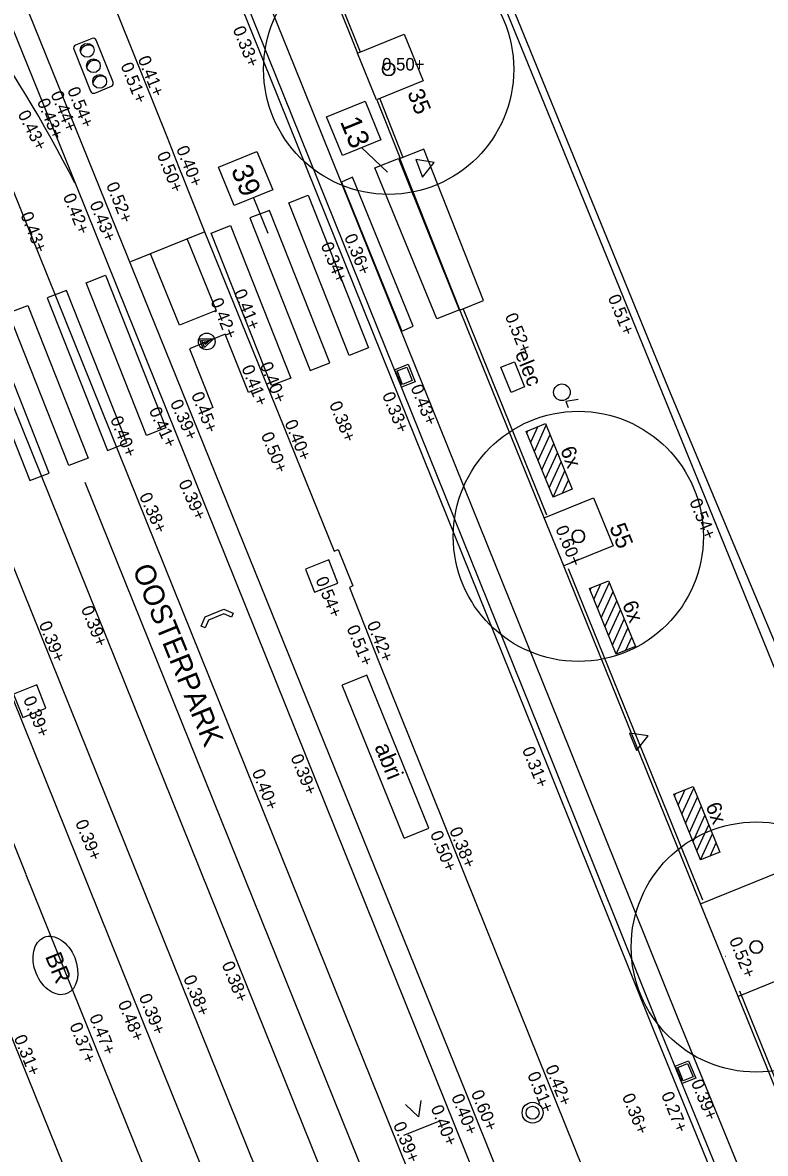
# Model space of a CAD drawing. Extents: x 122462 to 123306, y 485548 to 486417.
# Drawn here: x 122945.6 to 122963.41, y 485781.02 to 485808.14 of the extents above; entities that cross this region are included whole.
import ezdxf

# ---------------------------------------------------------------- set-up
doc = ezdxf.new("R2010")
doc.units = 0
for name, color, linetype in [('B meubilair trammast', 7, 'Continuous'), ('B-WE-AL-T25', 7, 'Continuous'), ('B-WE-GR-BOOM_BOOMDIAMETER', 7, 'Continuous'), ('B-WE-IE-MEUBILAIR_ELECTRAKAST', 7, 'Continuous'), ('B-WE-IE-MEUBILAIR_FIETSENREK-S', 7, 'Continuous'), ('B-WE-IE-TERREINAFSCHEIDING_KUNSTMATIG_HEKWERK-G', 7, 'Continuous'), ('B-WE-KL-ET_LS_OV_LICHTMAST-S', 7, 'Continuous'), ('B-WE-OG-HOOGTEPUNT-S', 7, 'Continuous'), ('B-WE-OG-TOPOGRAFIE_STRAATNAAM', 7, 'Continuous'), ('B-WE-RI-HWA_KOLK-S', 7, 'Continuous'), ('B-WE-RI-HWA_RIOOLPUT-S', 7, 'Continuous'), ('B-WE-VH-KANTOPSLUITING_OPSLUITBAND_100X200-G', 7, 'Continuous'), ('B-WE-VH-KANTOPSLUITING_TROTTOIRBAND_130 150-G', 7, 'Continuous'), ('B-WE-VH-MATERIAALGRENS-G', 7, 'Continuous'), ('B-WE-VH-MATERIAALGRENS_ASFALT-G', 7, 'Continuous'), ('B-WE-VW-MARKERING_LANGS_STREEP_30_15-30-G', 7, 'Continuous'), ('B-WE-VW-MARKERING_LANGS_STREEP_DOORGETROKKEN_010-G', 7, 'Continuous'), ('iba7-verkeersbord blauw', 7, 'Continuous'), ('iba7-verkeersbord rood', 7, 'Continuous'), ('N-WE-IE-MEUBILAIR_ABRI-S', 7, 'Continuous'), ('V boomranden', 7, 'Continuous'), ('V Langsstreep 030-015', 7, 'Continuous'), ('V markering figuratie', 7, 'Continuous'), ('V markering ononderbroken streep 10 cm', 7, 'Continuous'), ('V materiaalscheiding algemeen', 7, 'Continuous'), ('V meubilair trammast', 7, 'Continuous'), ('V meubilair verkeersbord', 7, 'Continuous'), ('V meubilair verkeerslicht', 7, 'Continuous'), ('V Rails', 7, 'Continuous'), ('V riool inspectieput', 7, 'Continuous'), ('V trottoirband 180-200x250 mm specie', 7, 'Continuous'), ('V-WE-GR-BOOM-S', 7, 'Continuous'), ('X-WE-AL-TEKENBLAD-S', 7, 'Continuous')]:
    doc.layers.add(name, color=color, linetype=linetype)

msp = doc.modelspace()

# ---------------------------------------------------------------- linework, layer by layer
at = {"layer": 'B meubilair trammast'}
msp.add_lwpolyline([(122960.157, 485791.095), (122960.326, 485790.678), (122960.603, 485791.033)], close=True, dxfattribs=at)
at = {"layer": 'B-WE-IE-MEUBILAIR_ELECTRAKAST'}
for p, q in [((122957.071, 485799.873), (122957.395, 485800.004)), ((122957.395, 485800.004), (122957.64, 485799.402)), ((122957.316, 485799.271), (122957.071, 485799.873)), ((122957.64, 485799.402), (122957.316, 485799.271))]:
    msp.add_line(p, q, dxfattribs=at)
at = {"layer": 'B-WE-IE-MEUBILAIR_FIETSENREK-S'}
for p, q in [((122957.679, 485798.333), (122958.142, 485798.522)), ((122958.32, 485796.759), (122957.679, 485798.333)), ((122957.696, 485798.291), (122957.723, 485798.352)), ((122957.785, 485798.073), (122957.955, 485798.446)), ((122957.874, 485797.854), (122958.159, 485798.48)), ((122958.142, 485798.522), (122958.783, 485796.947)), ((122957.963, 485797.635), (122958.248, 485798.26)), ((122958.052, 485797.416), (122958.337, 485798.042)), ((122958.141, 485797.197), (122958.426, 485797.823)), ((122958.231, 485796.978), (122958.516, 485797.603)), ((122958.32, 485796.759), (122958.605, 485797.385)), ((122958.783, 485796.947), (122958.32, 485796.759)), ((122958.551, 485796.853), (122958.694, 485797.166)), ((122959.192, 485794.564), (122959.655, 485794.753)), ((122959.655, 485794.753), (122960.296, 485793.178)), ((122959.833, 485792.989), (122959.192, 485794.564)), ((122959.209, 485794.522), (122959.237, 485794.582)), ((122959.298, 485794.303), (122959.468, 485794.676)), ((122959.388, 485794.085), (122959.673, 485794.711)), ((122959.477, 485793.865), (122959.762, 485794.491)), ((122959.566, 485793.646), (122959.851, 485794.272)), ((122959.655, 485793.428), (122959.94, 485794.054)), ((122959.744, 485793.208), (122960.029, 485793.834)), ((122959.833, 485792.989), (122960.118, 485793.615)), ((122960.065, 485793.084), (122960.207, 485793.397)), ((122960.296, 485793.178), (122959.833, 485792.989)), ((122961.218, 485789.632), (122961.681, 485789.82)), ((122961.859, 485788.057), (122961.218, 485789.632)), ((122961.235, 485789.59), (122961.262, 485789.65)), ((122961.324, 485789.371), (122961.494, 485789.744)), ((122961.413, 485789.152), (122961.698, 485789.778)), ((122961.681, 485789.82), (122962.322, 485788.246)), ((122961.502, 485788.933), (122961.787, 485789.559)), ((122961.591, 485788.714), (122961.876, 485789.34)), ((122961.68, 485788.495), (122961.965, 485789.121)), ((122961.77, 485788.276), (122962.055, 485788.902)), ((122961.859, 485788.057), (122962.144, 485788.683)), ((122962.322, 485788.246), (122961.859, 485788.057)), ((122962.09, 485788.151), (122962.233, 485788.464))]:
    msp.add_line(p, q, dxfattribs=at)
at = {"layer": 'B-WE-IE-TERREINAFSCHEIDING_KUNSTMATIG_HEKWERK-G'}
msp.add_lwpolyline([(122989.165, 485730.709), (122983.361, 485744.921), (122981.681, 485749.067), (122980.156, 485752.878), (122979.412, 485754.737), (122974.855, 485765.867), (122973.315, 485769.586), (122971.781, 485773.305), (122965.757, 485788.22), (122961.098, 485799.347), (122955.791, 485812.34), (122952.781, 485819.767), (122949.963, 485826.635), (122951.345, 485827.208)], dxfattribs=at)
at = {"layer": 'B-WE-KL-ET_LS_OV_LICHTMAST-S'}
msp.add_lwpolyline([(122958.924, 485799.101), (122958.629, 485799.048), (122958.686, 485798.909)], dxfattribs=at)
msp.add_circle((122958.534, 485799.273), 0.2, dxfattribs=at)
at = {"layer": 'B-WE-RI-HWA_KOLK-S'}
for p, q in [((122954.517, 485799.813), (122954.842, 485799.943)), ((122954.842, 485799.943), (122955.01, 485799.526)), ((122954.685, 485799.395), (122954.517, 485799.813)), ((122954.536, 485799.766), (122954.54, 485799.768)), ((122954.583, 485799.688), (122954.553, 485799.763)), ((122954.573, 485799.673), (122954.578, 485799.675)), ((122954.582, 485799.65), (122954.587, 485799.652)), ((122954.63, 485799.572), (122954.6, 485799.647)), ((122954.62, 485799.558), (122954.625, 485799.559)), ((122954.629, 485799.534), (122954.634, 485799.536)), ((122954.659, 485799.5), (122954.647, 485799.531)), ((122954.677, 485799.456), (122954.659, 485799.5)), ((122954.667, 485799.442), (122954.671, 485799.443)), ((122955.01, 485799.526), (122954.685, 485799.395)), ((122961.249, 485783.109), (122961.573, 485783.242)), ((122961.419, 485782.693), (122961.249, 485783.109)), ((122961.573, 485783.242), (122961.743, 485782.825)), ((122961.268, 485783.063), (122961.272, 485783.065)), ((122961.315, 485782.985), (122961.285, 485783.059)), ((122961.305, 485782.97), (122961.31, 485782.972)), ((122961.315, 485782.947), (122961.319, 485782.949)), ((122961.363, 485782.87), (122961.332, 485782.944)), ((122961.353, 485782.855), (122961.357, 485782.857)), ((122961.362, 485782.832), (122961.367, 485782.833)), ((122961.392, 485782.797), (122961.38, 485782.828)), ((122961.743, 485782.825), (122961.419, 485782.693)), ((122961.41, 485782.754), (122961.392, 485782.797)), ((122961.4, 485782.739), (122961.404, 485782.741))]:
    msp.add_line(p, q, dxfattribs=at)
for points in [[(122954.814, 485799.878), (122954.945, 485799.554), (122954.713, 485799.46), (122954.582, 485799.785)], [(122961.545, 485783.176), (122961.678, 485782.852), (122961.446, 485782.758), (122961.314, 485783.082)]]:
    msp.add_lwpolyline(points, close=True, dxfattribs=at)
for centre, start, end in [((122954.544, 485799.759), 21.9526, 111.9526), ((122954.574, 485799.685), 291.9526, 21.9526), ((122954.591, 485799.643), 21.9526, 111.9526), ((122954.621, 485799.569), 291.9526, 21.9526), ((122954.638, 485799.527), 21.9526, 111.9526), ((122954.667, 485799.453), 291.9526, 21.9526), ((122961.276, 485783.056), 22.213, 112.213), ((122961.306, 485782.982), 292.213, 22.213), ((122961.323, 485782.94), 22.213, 112.213), ((122961.353, 485782.866), 292.213, 22.213), ((122961.37, 485782.824), 22.213, 112.213), ((122961.401, 485782.75), 292.213, 22.213)]:
    msp.add_arc(centre, 0.01, start, end, dxfattribs=at)
at = {"layer": 'B-WE-RI-HWA_RIOOLPUT-S'}
msp.add_lwpolyline([(122953.16, 485794.696), (122952.94, 485795.254), (122952.382, 485795.034), (122952.602, 485794.476)], close=True, dxfattribs=at)
at = {"layer": 'B-WE-VH-KANTOPSLUITING_OPSLUITBAND_100X200-G'}
msp.add_lwpolyline([(122973.186, 485769.183), (122961.88, 485796.965), (122957.179, 485808.478), (122950.921, 485823.807), (122951.367, 485823.988)], dxfattribs=at)
for points in [[(122958.108, 485796.262), (122959.293, 485796.743), (122959.761, 485795.588), (122958.576, 485795.108)], [(122961.859, 485787.008), (122963.789, 485787.789), (122964.691, 485785.563), (122962.761, 485784.781)]]:
    msp.add_lwpolyline(points, close=True, dxfattribs=at)
at = {"layer": 'B-WE-VH-KANTOPSLUITING_TROTTOIRBAND_130 150-G'}
for points in [[(122944.788, 485793.338), (122945.622, 485791.289), (122948.972, 485782.968), (122953.472, 485771.818)], [(122944.02, 485787.037), (122960.779, 485745.561)]]:
    msp.add_lwpolyline(points, dxfattribs=at)
at = {"layer": 'B-WE-VH-MATERIAALGRENS-G'}
for points in [[(122958.108, 485796.262), (122956.423, 485800.42)], [(122961.326, 485784.244), (122958.46, 485791.369), (122955.04, 485799.854)], [(122961.859, 485787.008), (122958.57, 485795.123)], [(122965.926, 485776.976), (122962.763, 485784.779)], [(122983.898, 485728.575), (122964.99, 485775.27), (122961.325, 485784.246)]]:
    msp.add_lwpolyline(points, dxfattribs=at)
at = {"layer": 'B-WE-VH-MATERIAALGRENS_ASFALT-G'}
for points in [[(122954.438, 485799.608), (122957.857, 485791.126), (122960.723, 485784.001)], [(122960.723, 485784.001), (122964.388, 485775.026), (122983.295, 485728.331)]]:
    msp.add_lwpolyline(points, dxfattribs=at)
at = {"layer": 'B-WE-VW-MARKERING_LANGS_STREEP_30_15-30-G'}
for points in [[(122958.17, 485796.328), (122956.499, 485800.451)], [(122961.914, 485787.091), (122958.694, 485795.035)], [(122962.462, 485785.739), (122962.461, 485785.742)], [(122965.966, 485777.094), (122962.798, 485784.908)]]:
    msp.add_lwpolyline(points, dxfattribs=at)
at = {"layer": 'B-WE-VW-MARKERING_LANGS_STREEP_DOORGETROKKEN_010-G'}
for points in [[(122955.152, 485782.289), (122955.096, 485781.892), (122954.783, 485782.189)], [(122954.738, 485781.453), (122955.649, 485781.817)]]:
    msp.add_lwpolyline(points, dxfattribs=at)
at = {"layer": 'iba7-verkeersbord blauw'}
for radius in [0.25, 0.156]:
    msp.add_circle((122957.83, 485781.995), radius, dxfattribs=at)
msp.add_ellipse((122946.384, 485785.526), major_axis=(-0.273, 0.676), ratio=0.685994, dxfattribs=at)
at = {"layer": 'iba7-verkeersbord rood'}
for centre, radius in [((122954.378, 485807.018), 3), ((122954.378, 485807.018), 0.15), ((122958.928, 485795.816), 3), ((122958.928, 485795.816), 0.15), ((122963.195, 485785.968), 3), ((122963.195, 485785.968), 0.15)]:
    msp.add_circle(centre, radius, dxfattribs=at)
for centre, start, end in [((122954.378, 485807.018), 0, 180), ((122954.378, 485807.018), 180, 0), ((122958.928, 485795.816), 0, 180), ((122958.928, 485795.816), 180, 0), ((122963.195, 485785.968), 0, 180), ((122963.195, 485785.968), 180, 0)]:
    msp.add_arc(centre, 0.15, start, end, dxfattribs=at)
at = {"layer": 'N-WE-IE-MEUBILAIR_ABRI-S'}
msp.add_line((122954.748, 485788.577), (122953.26, 485792.249), dxfattribs=at)
msp.add_lwpolyline([(122954.748, 485788.577), (122955.343, 485788.818), (122953.856, 485792.49), (122953.26, 485792.249)], dxfattribs=at)
at = {"layer": 'V boomranden'}
msp.add_lwpolyline([(122953.633, 485807.408), (122954.753, 485807.862), (122955.208, 485806.738), (122954.088, 485806.285)], close=True, dxfattribs=at)
at = {"layer": 'V Langsstreep 030-015'}
for points in [[(122949.775, 485817.2), (122953.698, 485807.434)], [(122954.163, 485806.313), (122954.71, 485804.93)], [(122956.499, 485800.451), (122956.163, 485801.279)]]:
    msp.add_lwpolyline(points, dxfattribs=at)
at = {"layer": 'V markering figuratie'}
for p, q in [((122949.977, 485793.888), (122950.425, 485794.07)), ((122950.424, 485793.961), (122950.053, 485793.811)), ((122950.608, 485793.883), (122950.424, 485793.961)), ((122950.425, 485794.07), (122950.647, 485793.975)), ((122950.647, 485793.975), (122950.608, 485793.883)), ((122949.883, 485793.666), (122949.977, 485793.888)), ((122949.975, 485793.627), (122949.883, 485793.666)), ((122950.053, 485793.811), (122949.975, 485793.627))]:
    msp.add_line(p, q, dxfattribs=at)
for points in [[(122956.059, 485801.238), (122955.53, 485801.032), (122954.044, 485804.657), (122954.613, 485804.878), (122956.066, 485801.248)], [(122953.514, 485804.435), (122953.243, 485804.314), (122954.693, 485800.735), (122954.964, 485800.856), (122953.514, 485804.435)]]:
    msp.add_lwpolyline(points, dxfattribs=at)
for points in [[(122953.429, 485800.158), (122951.983, 485803.817), (122952.449, 485803.998), (122953.895, 485800.339)], [(122951.051, 485803.455), (122952.497, 485799.796), (122952.963, 485799.977), (122951.517, 485803.636)], [(122951.565, 485799.433), (122950.119, 485803.092), (122950.585, 485803.273), (122952.031, 485799.614)], [(122948.566, 485798.239), (122947.12, 485801.898), (122947.586, 485802.08), (122949.032, 485798.421)], [(122946.188, 485801.536), (122947.634, 485797.877), (122948.1, 485798.058), (122946.654, 485801.717)], [(122946.702, 485797.515), (122945.256, 485801.174), (122945.722, 485801.355), (122947.168, 485797.696)], [(122944.324, 485800.812), (122945.77, 485797.153), (122946.236, 485797.334), (122944.79, 485800.993)]]:
    msp.add_lwpolyline(points, close=True, dxfattribs=at)
at = {"layer": 'V markering ononderbroken streep 10 cm'}
msp.add_lwpolyline([(122960.179, 485764.685), (122947.097, 485797.105)], dxfattribs=at)
at = {"layer": 'V materiaalscheiding algemeen'}
for points in [[(122955.04, 485799.854), (122952.121, 485807.096), (122947.132, 485819.421), (122944.074, 485826.926), (122939.266, 485838.678), (122934.779, 485849.488)], [(122934.198, 485849.192), (122938.665, 485838.43), (122943.472, 485826.68), (122946.53, 485819.177), (122951.518, 485806.853), (122954.438, 485799.608)], [(122949.71, 485817.174), (122953.633, 485807.408)], [(122954.098, 485806.287), (122954.645, 485804.904)], [(122956.099, 485801.253), (122956.654, 485801.476), (122955.221, 485805.101), (122954.652, 485804.876)], [(122956.423, 485800.42), (122956.087, 485801.248), (122954.64, 485804.902)], [(122949.544, 485802.948), (122950.237, 485801.233), (122949.36, 485800.88), (122948.668, 485802.595)], [(122951.25, 485799.367), (122951.019, 485799.271), (122950.452, 485800.669), (122949.597, 485800.313), (122950.164, 485798.904), (122949.857, 485798.773)]]:
    msp.add_lwpolyline(points, dxfattribs=at)
at = {"layer": 'V meubilair trammast'}
msp.add_lwpolyline([(122955.026, 485804.852), (122955.191, 485804.433), (122955.471, 485804.786)], close=True, dxfattribs=at)
at = {"layer": 'V meubilair verkeersbord'}
msp.add_lwpolyline([(122949.932, 485800.323), (122949.837, 485800.557), (122950.184, 485800.561), (122949.963, 485800.348), (122949.894, 485800.519), (122950.106, 485800.529), (122949.978, 485800.417), (122949.953, 485800.48), (122949.994, 485800.483), (122950.041, 485800.501)], dxfattribs=at)
msp.add_circle((122950.013, 485800.491), 0.2, dxfattribs=at)
at = {"layer": 'V meubilair verkeerslicht'}
for points in [[(122946.823, 485807.5), (122947.228, 485806.491)], [(122947.264, 485807.759), (122946.864, 485807.598)], [(122947.767, 485806.708), (122947.362, 485807.717)], [(122947.326, 485806.449), (122947.726, 485806.61)]]:
    msp.add_lwpolyline(points, dxfattribs=at)
for centre in [(122947.146, 485807.474), (122947.295, 485807.104), (122947.446, 485806.728)]:
    msp.add_circle(centre, 0.166, dxfattribs=at)
for centre, radius, start, end in [((122946.892, 485807.528), 0.075, 111.8885, 201.8885), ((122947.175, 485807.41), 0.191, 55.8389, 172.8124), ((122947.292, 485807.689), 0.075, 21.8885, 111.8885), ((122947.324, 485807.04), 0.191, 55.8389, 172.8124), ((122947.475, 485806.664), 0.191, 55.8389, 172.8124), ((122947.698, 485806.68), 0.075, 291.8885, 21.8885), ((122947.298, 485806.519), 0.075, 201.8885, 291.8885)]:
    msp.add_arc(centre, radius, start, end, dxfattribs=at)
at = {"layer": 'V Rails'}
for points in [[(122927.47, 485843.218), (122942.882, 485805.099), (122954.784, 485775.587)], [(122926.135, 485842.678), (122941.546, 485804.559), (122953.448, 485775.05)], [(122936.708, 485829.325), (122946.878, 485804.229), (122962.418, 485765.659)], [(122935.374, 485828.785), (122945.542, 485803.689), (122961.082, 485765.121)]]:
    msp.add_lwpolyline(points, dxfattribs=at)
msp.add_arc((122916.417, 485788.786), 34.154, 26.9894, 43.2566, dxfattribs=at)
at = {"layer": 'V riool inspectieput'}
msp.add_lwpolyline([(122946.158, 485791.696), (122945.938, 485792.255), (122945.38, 485792.035), (122945.6, 485791.476)], close=True, dxfattribs=at)
at = {"layer": 'V trottoirband 180-200x250 mm specie'}
for points in [[(122954.517, 485799.813), (122951.657, 485806.909), (122946.669, 485819.233), (122943.611, 485826.737), (122938.804, 485838.487), (122934.332, 485849.261)], [(122945.681, 485813.801), (122949.053, 485805.408), (122949.395, 485804.544)], [(122947.593, 485803.814), (122945.744, 485808.38)], [(122949.394, 485804.549), (122949.965, 485803.107), (122951.74, 485798.736)], [(122949.942, 485798.01), (122947.593, 485803.812)], [(122945.686, 485787.704), (122940.949, 485799.528), (122940.353, 485800.805), (122939.533, 485802.635), (122939.166, 485803.569)], [(122949.969, 485803.119), (122948.186, 485802.4)]]:
    msp.add_lwpolyline(points, dxfattribs=at)
at = {"layer": 'V-WE-GR-BOOM-S'}
for points in [[(122960.862, 485784.057), (122957.996, 485791.182), (122954.517, 485799.813)], [(122951.74, 485798.736), (122953.069, 485795.465), (122953.163, 485795.502), (122953.521, 485794.633), (122953.438, 485794.593), (122954.14, 485792.811), (122957.738, 485783.873), (122965.696, 485764.131), (122970.276, 485752.884), (122971.001, 485751.054), (122971.388, 485750.095)], [(122969.614, 485749.271), (122963.986, 485763.138), (122956.242, 485782.448), (122949.942, 485798.01)], [(122962.728, 485745.564), (122954.408, 485766.082), (122945.68, 485787.702)], [(122983.435, 485728.388), (122964.527, 485775.082), (122960.862, 485784.057)]]:
    msp.add_lwpolyline(points, dxfattribs=at)
at = {"layer": 'X-WE-AL-TEKENBLAD-S'}
for p, q in [((122953.73, 485805.141), (122954.348, 485804.551)), ((122951.134, 485803.936), (122951.481, 485803.085))]:
    msp.add_line(p, q, dxfattribs=at)
for points in [[(122953.815, 485806.256), (122954.193, 485805.33), (122953.267, 485804.952), (122952.889, 485805.878)], [(122951.219, 485805.051), (122951.597, 485804.125), (122950.671, 485803.748), (122950.293, 485804.674)]]:
    msp.add_lwpolyline(points, close=True, dxfattribs=at)

# ---------------------------------------------------------------- texts
at = {"layer": 'B-WE-AL-T25'}
for p in [(122958.487, 485797.895), (122959.975, 485794.19), (122961.974, 485789.355)]:
    msp.add_text('6x', height=0.36, rotation=291.8049, dxfattribs=at).set_placement(p)
at = {"layer": 'B-WE-GR-BOOM_BOOMDIAMETER'}
for s, rotation, p in [('35', 291.5796, (122954.819, 485806.454)), ('55', 292.0637, (122959.665, 485796.037))]:
    msp.add_text(s, height=0.4, rotation=rotation, dxfattribs=at).set_placement(p)
at = {"layer": 'B-WE-IE-MEUBILAIR_ELECTRAKAST'}
msp.add_text('elec', height=0.36, rotation=292.0419, dxfattribs=at).set_placement((122957.401, 485800.201))
at = {"layer": 'B-WE-OG-HOOGTEPUNT-S'}
for s, rotation, p in [('0.33+', 292.0551, (122950.632, 485807.983)), ('0.41+', 291.9224, (122948.355, 485807.271)), ('0.51+', 291.9224, (122947.942, 485807.112)), ('0.44+', 292.1209, (122946.264, 485806.428)), ('0.54+', 292.1209, (122946.662, 485806.525)), ('0.43+', 292.1209, (122945.937, 485806.25)), ('0.43+', 297.2424, (122945.47, 485805.944)), ('0.40+', 291.9224, (122949.276, 485805.114)), ('0.50+', 291.9224, (122948.811, 485804.977)), ('0.52+', 292.1209, (122947.595, 485804.243)), ('0.42+', 292.1209, (122946.56, 485803.973)), ('0.43+', 292.1209, (122947.199, 485803.791)), ('0.43+', 292.1209, (122945.539, 485803.528)), ('0.36+', 292.2634, (122953.307, 485803.001)), ('0.34+', 292.2634, (122952.742, 485802.801)), ('0.42+', 292.2634, (122950.098, 485801.463)), ('0.41+', 292.2634, (122950.657, 485801.674)), ('0.51+', 292.2498, (122959.629, 485801.546)), ('0.52+', 292.2498, (122957.161, 485801.101)), ('0.41+', 291.8578, (122950.843, 485799.857)), ('0.40+', 291.8578, (122951.285, 485799.931)), ('0.43+', 292.2634, (122954.898, 485799.388)), ('0.39+', 294.4051, (122949.128, 485799.018)), ('0.45+', 291.8578, (122949.637, 485799.212)), ('0.33+', 292.2634, (122954.215, 485799.209)), ('0.41+', 294.4051, (122948.621, 485798.839)), ('0.38+', 292.2634, (122952.946, 485798.987)), ('0.40+', 291.8578, (122947.694, 485798.63)), ('0.40+', 292.2634, (122951.876, 485798.543)), ('0.50+', 292.2634, (122951.31, 485798.246)), ('0.39+', 294.4051, (122949.329, 485797.099)), ('0.38+', 294.4051, (122948.387, 485796.785)), ('0.54+', 292.2498, (122961.585, 485796.653)), ('0.60+', 292.0551, (122958.374, 485796.006)), ('0.54+', 292.0551, (122952.618, 485794.781)), ('0.39+', 292.0494, (122946.992, 485794.083)), ('0.39+', 292.0494, (122945.981, 485793.712)), ('0.51+', 292.0562, (122953.364, 485793.618)), ('0.42+', 292.0562, (122953.848, 485793.716)), ('0.39+', 292.0494, (122945.606, 485791.914)), ('0.31+', 292.0551, (122957.572, 485790.703)), ('0.39+', 292.0562, (122952.019, 485790.523)), ('0.40+', 292.0562, (122951.093, 485790.166)), ('0.39+', 292.0494, (122946.854, 485788.953)), ('0.38+', 292.0562, (122955.828, 485788.775)), ('0.50+', 292.0562, (122955.366, 485788.686)), ('0.52+', 292.0551, (122962.538, 485786.137)), ('0.38+', 292.0562, (122950.368, 485785.553)), ('0.38+', 292.0562, (122949.446, 485785.225)), ('0.39+', 292.0562, (122948.38, 485784.777)), ('0.48+', 292.0562, (122947.877, 485784.618)), ('0.47+', 292.0562, (122947.19, 485784.29)), ('0.37+', 292.0562, (122946.717, 485784.087)), ('0.31+', 292.0015, (122945.382, 485783.793)), ('0.42+', 292.0562, (122958.129, 485783.071)), ('0.51+', 292.0562, (122957.699, 485782.908)), ('0.39+', 292.213, (122961.625, 485782.723)), ('0.40+', 292.0562, (122955.875, 485782.375)), ('0.60+', 292.0562, (122956.348, 485782.469)), ('0.36+', 292.213, (122959.97, 485782.386)), ('0.27+', 292.213, (122960.907, 485782.427)), ('0.40+', 292.0562, (122955.381, 485782.109)), ('0.39+', 292.0562, (122954.48, 485781.706))]:
    msp.add_text(s, height=0.3, rotation=rotation, dxfattribs=at).set_placement(p)
msp.add_text('0.50+', height=0.3, dxfattribs=at).set_placement((122954.221, 485806.99))
at = {"layer": 'B-WE-OG-TOPOGRAFIE_STRAATNAAM'}
msp.add_text('OOSTERPARK', height=0.5, rotation=292.0555, dxfattribs=at).set_placement((122948.226, 485795.037))
at = {"layer": 'iba7-verkeersbord blauw'}
msp.add_text('BR', height=0.4, rotation=291.9844, dxfattribs=at).set_placement((122946.13, 485785.745))
at = {"layer": 'N-WE-IE-MEUBILAIR_ABRI-S'}
msp.add_text('abri', height=0.4, rotation=292.0551, dxfattribs=at).set_placement((122954.033, 485790.774))
at = {"layer": 'X-WE-AL-TEKENBLAD-S'}
for s, p in [('13', (122953.205, 485805.766)), ('39', (122950.589, 485804.609))]:
    msp.add_text(s, height=0.5, rotation=292.187, dxfattribs=at).set_placement(p)

doc.saveas('drawing.dxf')
